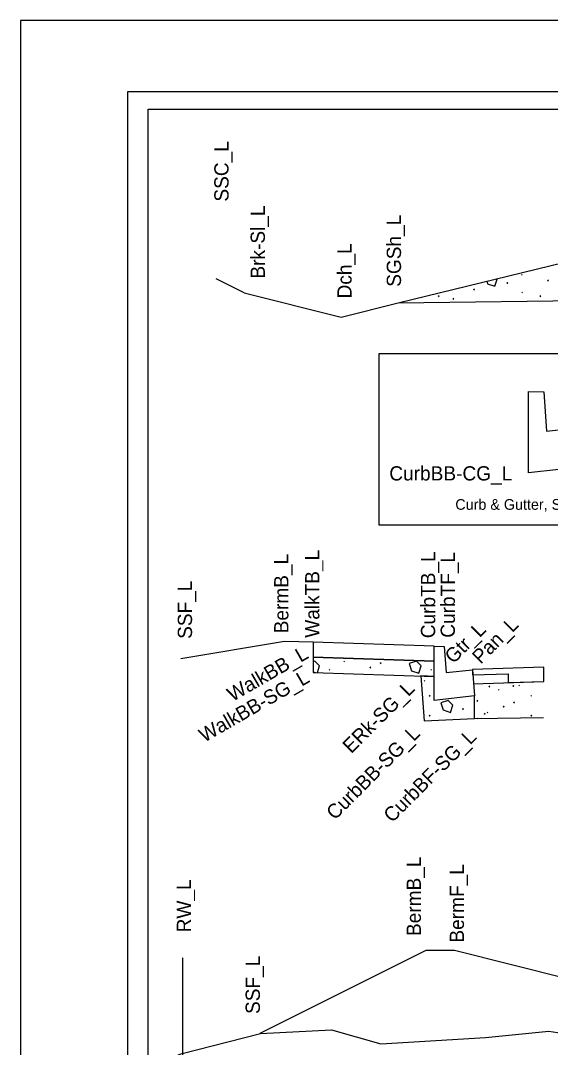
# Model space of a CAD drawing. Extents: x 0 to 1.42, y 0 to 0.92.
# Drawn here: x 0 to 0.309, y 0.317 to 0.917 of the extents above; entities that cross this region are included whole.
import ezdxf

# ---------------------------------------------------------------- set-up
doc = ezdxf.new("R2010")
doc.units = 0
for name, color, linetype in [('#plot_shape', 7, 'Continuous'), ('Level 63', 7, 'Continuous'), ('P_ODOT_PLAN_Border', 7, 'Continuous'), ('P_RDWY_PLAN_Detail', 7, 'Continuous'), ('P_RDWY_PLAN_DetailTx', 7, 'Continuous')]:
    doc.layers.add(name, color=color, linetype=linetype)

msp = doc.modelspace()

# ---------------------------------------------------------------- linework, layer by layer
at = {"layer": '#plot_shape'}
msp.add_lwpolyline([(0, 0), (1.41667, 0), (1.41667, 0.91667), (0, 0.91667)], close=True, dxfattribs=at)
msp.add_lwpolyline([(0, 0), (1.41667, 0), (1.41667, 0.91667), (0, 0.91667)], close=True, dxfattribs=at)
at = {"layer": 'Level 63'}
for points in [[(0.91493, 0.24948), (0.07445, 0.24948), (0.07445, 0.86481), (0.91493, 0.86481)], [(0.41534, 0.62173), (0.20935, 0.62173), (0.20935, 0.72218), (0.41534, 0.72218)]]:
    msp.add_lwpolyline(points, close=True, dxfattribs=at)
at = {"layer": 'P_ODOT_PLAN_Border'}
for p, q in [((1.30879, 0.875), (0.0625, 0.875)), ((0.0625, 0.875), (0.0625, 0.0419)), ((1.30879, 0.875), (0.0625, 0.875)), ((1.30879, 0.875), (0.0625, 0.875)), ((0.0625, 0.875), (0.0625, 0.0419)), ((1.30879, 0.875), (0.0625, 0.875))]:
    msp.add_line(p, q, dxfattribs=at)
msp.add_lwpolyline([(0.0625, 0.04167), (1.39583, 0.04167), (1.39583, 0.875), (0.0625, 0.875)], close=True, dxfattribs=at)
msp.add_lwpolyline([(0.0625, 0.04167), (1.39583, 0.04167), (1.39583, 0.875), (0.0625, 0.875)], close=True, dxfattribs=at)
msp.add_lwpolyline([(0.0625, 0.875), (0.0625, 0.875), (0.0625, 0.0419)], dxfattribs=at)
msp.add_lwpolyline([(0.0625, 0.875), (0.0625, 0.875), (0.0625, 0.0419)], dxfattribs=at)
at = {"layer": 'P_RDWY_PLAN_Detail'}
for p, q in [((0.29285, 0.76834), (0.29239, 0.76788)), ((0.29239, 0.76834), (0.29285, 0.76788)), ((0.13058, 0.7575), (0.1142, 0.76569)), ((0.28433, 0.76354), (0.28387, 0.76308)), ((0.28387, 0.76354), (0.28433, 0.76308)), ((0.30818, 0.76494), (0.30772, 0.76447)), ((0.30772, 0.76494), (0.30818, 0.76447)), ((0.26497, 0.75967), (0.26451, 0.75921)), ((0.26451, 0.75967), (0.26497, 0.75921)), ((0.29316, 0.75797), (0.2927, 0.7575)), ((0.2927, 0.75797), (0.29316, 0.7575)), ((0.24438, 0.7558), (0.24391, 0.75534)), ((0.24391, 0.7558), (0.24438, 0.75534)), ((0.25289, 0.75425), (0.25243, 0.75379)), ((0.25243, 0.75425), (0.25289, 0.75379)), ((0.30369, 0.7558), (0.30323, 0.75534)), ((0.30323, 0.7558), (0.30369, 0.75534)), ((0.18913, 0.54229), (0.18867, 0.54182)), ((0.18867, 0.54229), (0.18913, 0.54182)), ((0.2105, 0.54136), (0.21004, 0.54089)), ((0.21004, 0.54136), (0.2105, 0.54089)), ((0.17077, 0.53612), (0.17197, 0.53572)), ((0.18061, 0.53749), (0.18015, 0.53702)), ((0.18015, 0.53749), (0.18061, 0.53702)), ((0.20446, 0.53888), (0.204, 0.53842)), ((0.204, 0.53888), (0.20446, 0.53842)), ((0.23993, 0.53749), (0.23946, 0.53702)), ((0.23946, 0.53749), (0.23993, 0.53702)), ((0.23603, 0.5311), (0.23556, 0.53064)), ((0.23556, 0.5311), (0.23603, 0.53064)), ((0.2643, 0.52906), (0.30556, 0.53047)), ((0.2914, 0.52836), (0.29094, 0.52789)), ((0.29094, 0.52836), (0.2914, 0.52789)), ((0.23906, 0.52232), (0.23859, 0.52185)), ((0.23859, 0.52232), (0.23906, 0.52185)), ((0.2739, 0.52774), (0.27344, 0.52727)), ((0.27344, 0.52774), (0.2739, 0.52727)), ((0.27948, 0.52572), (0.27901, 0.52526)), ((0.27901, 0.52572), (0.27948, 0.52526)), ((0.28784, 0.52805), (0.28738, 0.52758)), ((0.28738, 0.52805), (0.28784, 0.52758)), ((0.29837, 0.52232), (0.29791, 0.52185)), ((0.29791, 0.52232), (0.29837, 0.52185)), ((0.26694, 0.51937), (0.26647, 0.51891)), ((0.26647, 0.51937), (0.26694, 0.51891)), ((0.28831, 0.51844), (0.28784, 0.51798)), ((0.28784, 0.51844), (0.28831, 0.51798)), ((0.23906, 0.5107), (0.23859, 0.51024)), ((0.23859, 0.5107), (0.23906, 0.51024)), ((0.25842, 0.51457), (0.25795, 0.51411)), ((0.25795, 0.51457), (0.25842, 0.51411)), ((0.27121, 0.51181), (0.27075, 0.51134)), ((0.27075, 0.51181), (0.27121, 0.51134)), ((0.27292, 0.51258), (0.27245, 0.51212)), ((0.27245, 0.51258), (0.27292, 0.51212)), ((0.28227, 0.51597), (0.2818, 0.5155)), ((0.2818, 0.51597), (0.28227, 0.5155)), ((0.29837, 0.5107), (0.29791, 0.51024)), ((0.29791, 0.5107), (0.29837, 0.51024)), ((0.26724, 0.509), (0.26678, 0.50853)), ((0.26678, 0.509), (0.26724, 0.50853))]:
    msp.add_line(p, q, dxfattribs=at)
for points in [[(0.13058, 0.7575), (0.18718, 0.74335), (0.22051, 0.75168), (0.35768, 0.78529), (0.39102, 0.78596), (0.49102, 0.78796), (0.59102, 0.78996)], [(0.27219, 0.76434), (0.27272, 0.76277), (0.2769, 0.76138), (0.27829, 0.76556), (0.27807, 0.76578)], [(0.22051, 0.75168), (0.34102, 0.75329), (0.59102, 0.75662)], [(0.17076, 0.55344), (0.15409, 0.55378), (0.09361, 0.5437)], [(0.17329, 0.53565), (0.17457, 0.5395), (0.17179, 0.54229), (0.17078, 0.54195)], [(0.26502, 0.50873), (0.30528, 0.50935)], [(0.08341, 0.30835), (0.09362, 0.31287), (0.14013, 0.32468), (0.18147, 0.32689), (0.21026, 0.31877), (0.27153, 0.32246), (0.30844, 0.32615), (0.35642, 0.31877), (0.44858, 0.3227), (0.57023, 0.38352), (0.66131, 0.38534)], [(0.38669, 0.36485), (0.35335, 0.35651), (0.32002, 0.35651), (0.25335, 0.37318), (0.23669, 0.37318), (0.13962, 0.32465)]]:
    msp.add_lwpolyline(points, dxfattribs=at)
for points in [[(0.29659, 0.69991), (0.30543, 0.69961), (0.30712, 0.67671), (0.33024, 0.67931), (0.33194, 0.6563), (0.29659, 0.65233)], [(0.24146, 0.55106), (0.17076, 0.55344), (0.17077, 0.54461), (0.24146, 0.54222)], [(0.24146, 0.55106), (0.24735, 0.55086), (0.24848, 0.53559), (0.26389, 0.53733), (0.26502, 0.52199), (0.24146, 0.51934)], [(0.24146, 0.54222), (0.17077, 0.54461), (0.17078, 0.53577), (0.24146, 0.53338)], [(0.2325, 0.53532), (0.23389, 0.5395), (0.2311, 0.54229), (0.22692, 0.54089), (0.22831, 0.53671)], [(0.30556, 0.53872), (0.26389, 0.53747), (0.26389, 0.53434), (0.28472, 0.53496), (0.28472, 0.52984), (0.30556, 0.53047)], [(0.26502, 0.52199), (0.24146, 0.51934), (0.24146, 0.53338), (0.23362, 0.53365), (0.23557, 0.50741), (0.26502, 0.50873)], [(0.25098, 0.5124), (0.25238, 0.51659), (0.24959, 0.51937), (0.24541, 0.51798), (0.2468, 0.5138)]]:
    msp.add_lwpolyline(points, close=True, dxfattribs=at)
at = {"layer": 'P_RDWY_PLAN_DetailTx'}
msp.add_line((0.09483, 0.2878), (0.09483, 0.36902), dxfattribs=at)

# ---------------------------------------------------------------- texts
at = {"layer": 'P_RDWY_PLAN_Detail'}
msp.add_text('Curb & Gutter, Standard Inset', height=0.00625, dxfattribs=at).set_placement((0.25386, 0.63076))
at = {"layer": 'P_RDWY_PLAN_DetailTx'}
for s, rotation, p in [('SSC_L', 90, (0.12146, 0.81087)), ('Brk-Sl_L', 90, (0.14266, 0.76588)), ('SGSh_L', 90, (0.22214, 0.76107)), ('Dch_L', 90, (0.19328, 0.75426)), ('WalkTB_L', 90, (0.17447, 0.55599)), ('CurbTB_L', 90, (0.24208, 0.55571)), ('BermB_L', 90, (0.15639, 0.55858)), ('CurbTF_L', 90, (0.2536, 0.55599)), ('SSF_L', 90, (0.10014, 0.55533)), ('Pan_L', 45, (0.26865, 0.54015)), ('Gtr_L', 45, (0.25268, 0.54036)), ('WalkBB_L', 30, (0.12377, 0.51845)), ('WalkBB-SG_L', 30, (0.10728, 0.49454)), ('ERk-SG_L', 45, (0.1931, 0.48795)), ('CurbBB-SG_L', 45, (0.18352, 0.44905)), ('CurbBF-SG_L', 45, (0.21694, 0.44749)), ('BermB_L', 90, (0.23374, 0.38169)), ('BermF_L', 90, (0.2589, 0.37785)), ('RW_L', 90, (0.09954, 0.38382)), ('SSF_L', 90, (0.13973, 0.33613))]:
    msp.add_text(s, height=0.00833, rotation=rotation, dxfattribs=at).set_placement(p)
msp.add_text('CurbBB-CG_L', height=0.00833, dxfattribs=at).set_placement((0.21529, 0.64788))

doc.saveas('drawing.dxf')
